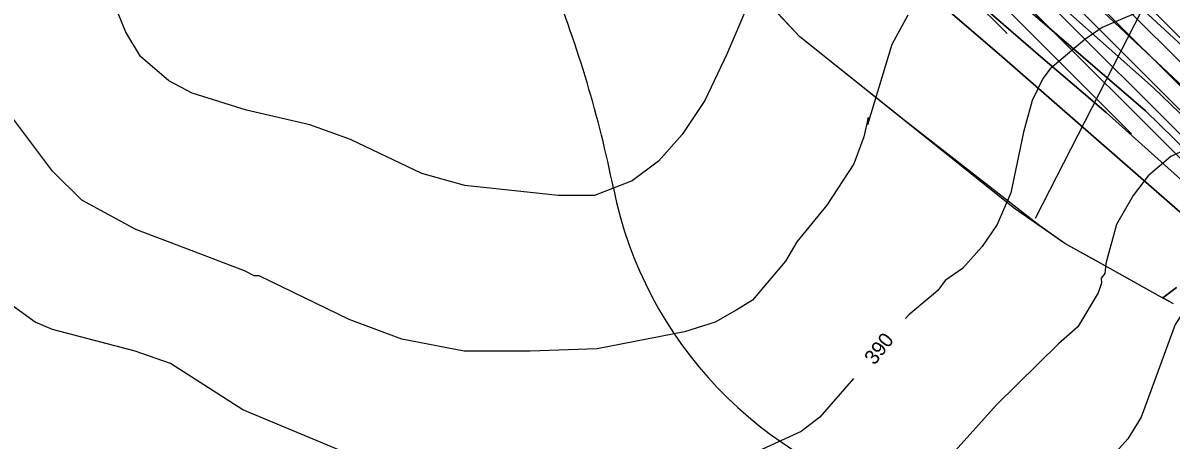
# Model space of a CAD drawing. Extents: x -510989 to -501240, y -1184665 to -1176098.
# Drawn here: x -506024.9 to -505553.2, y -1182373.4 to -1182202.2 of the extents above; entities that cross this region are included whole.
import ezdxf

# ---------------------------------------------------------------- set-up
doc = ezdxf.new("R2010")
doc.units = 0
for name, color, linetype in [('NAVRH_interakcni_prvky', 7, 'Continuous'), ('NAVRH_rozvodnice', 7, 'Continuous'), ('orna_puda', 7, 'Continuous'), ('ostatni_plocha_x_ostatni_komunikace', 7, 'Continuous'), ('popis', 7, 'Continuous'), ('STAV_erozne_ohrozene_plochy', 7, 'Continuous'), ('STAV_povodi', 7, 'Continuous'), ('vrstevnice_01', 7, 'Continuous'), ('vrstevnice_02', 7, 'Continuous'), ('vrstevnice_04', 7, 'Continuous')]:
    doc.layers.add(name, color=color, linetype=linetype)

msp = doc.modelspace()

# ---------------------------------------------------------------- linework, layer by layer
at = {"layer": 'NAVRH_interakcni_prvky'}
msp.add_lwpolyline([(-505608.99, -1182282.38), (-505565.31, -1182197.02), (-505541.49, -1182095.78), (-505537.52, -1182014.39), (-505537.52, -1181958.81), (-505551.42, -1181861.54), (-505543.48, -1181770.22), (-505601.05, -1181698.76)], dxfattribs=at)
at = {"layer": 'NAVRH_rozvodnice'}
for centre, radius, start, end in [((-506266.56, -1182367.95), 494.03, 11.4357, 21.798), ((-505619.19, -1182237), 166.46, 191.4357, 255.9859)]:
    msp.add_arc(centre, radius, start, end, dxfattribs=at)
at = {"layer": 'orna_puda'}
for points in [[(-505545.18, -1182214.83), (-505580.26, -1182182.28), (-505617.05, -1182149.56), (-505650.43, -1182121.46), (-505663.06, -1182110.4), (-505685.45, -1182090.8), (-505702.98, -1182074.96), (-505722.9, -1182057.01), (-505739.01, -1182040.64), (-505766.39, -1182010.41), (-505790.25, -1181981.36), (-505822.98, -1181943.35), (-505848.75, -1181914.84), (-505840.33, -1181901.77), (-505808.27, -1181940.23), (-505753.43, -1182008.51), (-505740.4, -1182022.58), (-505726.94, -1182036.86), (-505708.92, -1182054.97), (-505689.48, -1182072.92), (-505655.68, -1182102.08), (-505599.05, -1182150.98), (-505563.19, -1182182.97), (-505534.54, -1182209.27)], [(-505534.87, -1182240.97), (-505580.88, -1182197.95), (-505612.57, -1182169.78), (-505636.02, -1182148.91), (-505670.25, -1182118.51), (-505726.77, -1182068.32), (-505737.36, -1182058.02), (-505776.11, -1182017), (-505799.34, -1181987.39), (-505823.67, -1181958.67), (-505854.51, -1181923.82), (-505848.75, -1181914.84), (-505822.98, -1181943.35), (-505790.25, -1181981.36), (-505766.39, -1182010.41), (-505739.01, -1182040.64), (-505722.9, -1182057.01), (-505702.98, -1182074.96), (-505685.45, -1182090.8), (-505663.06, -1182110.4), (-505650.43, -1182121.46), (-505617.05, -1182149.56), (-505580.26, -1182182.28), (-505545.18, -1182214.83)], [(-505528.59, -1182272.56), (-505563.68, -1182238.3), (-505630.74, -1182180.48), (-505717.08, -1182105.45), (-505744.55, -1182080.37), (-505770.4, -1182053.98), (-505791.64, -1182029.89), (-505849.55, -1181961.49), (-505856.49, -1181953.98), (-505865.69, -1181948.03), (-505859.57, -1181935.79), (-505834.18, -1181962.22), (-505808.51, -1181992.89), (-505788.62, -1182017.4), (-505773.33, -1182035.16), (-505757.76, -1182051.76), (-505740.41, -1182069.28), (-505723.88, -1182084.02), (-505700.69, -1182105.62), (-505677.04, -1182126.17), (-505661.81, -1182139.41), (-505615.05, -1182180.23), (-505560.4, -1182228.84), (-505539.1, -1182249.38)], [(-505537.28, -1182277.15), (-505579.93, -1182239.02), (-505607.85, -1182215.08), (-505651.61, -1182177.07), (-505666.68, -1182164.52), (-505700.29, -1182135.24), (-505743.49, -1182096.79), (-505760.67, -1182080.74), (-505780.03, -1182061.47), (-505816.71, -1182018.56), (-505850.67, -1181978.46), (-505871.44, -1181958.44), (-505865.69, -1181948.03), (-505856.49, -1181953.98), (-505849.55, -1181961.49), (-505791.64, -1182029.89), (-505770.4, -1182053.98), (-505744.55, -1182080.37), (-505717.08, -1182105.45), (-505630.74, -1182180.48), (-505563.68, -1182238.3), (-505528.59, -1182272.56)], [(-505505.38, -1182318.31), (-505623.88, -1182215), (-505682.19, -1182164.88), (-505732.29, -1182121.93), (-505752.85, -1182103.56), (-505766.92, -1182090.9), (-505796.61, -1182059.91), (-505846.92, -1182000.9), (-505876.17, -1181968.64), (-505871.44, -1181958.44), (-505850.67, -1181978.46), (-505816.71, -1182018.56), (-505780.03, -1182061.47), (-505760.67, -1182080.74), (-505743.49, -1182096.79), (-505700.29, -1182135.24), (-505666.68, -1182164.52), (-505651.61, -1182177.07), (-505607.85, -1182215.08), (-505579.93, -1182239.02), (-505537.28, -1182277.15)], [(-505682.19, -1182164.88), (-505623.88, -1182215), (-505505.38, -1182318.31)], [(-505551.03, -1182310.8), (-505556.64, -1182315.12), (-505557.61, -1182314.6), (-505570.68, -1182307.26), (-505596.82, -1182292.75), (-505617.49, -1182278.33), (-505705.75, -1182207.82), (-505744.09, -1182166.53)], [(-505539.1, -1182249.38), (-505560.4, -1182228.84), (-505615.05, -1182180.23)], [(-505580.88, -1182197.95), (-505534.87, -1182240.97)]]:
    msp.add_lwpolyline(points, dxfattribs=at)
at = {"layer": 'ostatni_plocha_x_ostatni_komunikace'}
msp.add_lwpolyline([(-505552.97, -1182317.1), (-505556.64, -1182315.12), (-505551.03, -1182310.8)], dxfattribs=at)
at = {"layer": 'popis'}
msp.add_lwpolyline([(-505552.21, -1182317.51), (-505557.61, -1182314.6), (-505583.75, -1182300.01), (-505596.82, -1182292.75), (-505607.16, -1182285.54), (-505661.62, -1182243.07), (-505705.75, -1182207.82), (-505755.48, -1182155.02)], dxfattribs=at)
at = {"layer": 'STAV_erozne_ohrozene_plochy'}
for p, q in [((-505764.49, -1181993.31), (-505399.41, -1182358.39)), ((-505767.1, -1182000.6), (-505413.84, -1182353.86)), ((-505769.71, -1182007.89), (-505428.27, -1182349.33)), ((-505772.31, -1182015.18), (-505442.7, -1182344.8)), ((-505774.92, -1182022.48), (-505467.22, -1182330.18)), ((-505777.53, -1182029.77), (-505518.33, -1182288.97)), ((-505780.14, -1182037.06), (-505569.44, -1182247.76)), ((-505782.75, -1182044.35), (-505620.55, -1182206.55))]:
    msp.add_line(p, q, dxfattribs=at)
at = {"layer": 'STAV_povodi'}
for centre, radius, start, end in [((-506266.56, -1182367.95), 494.03, 11.4357, 21.798), ((-505619.19, -1182237), 166.46, 191.4357, 255.9859)]:
    msp.add_arc(centre, radius, start, end, dxfattribs=at)
at = {"layer": 'vrstevnice_01'}
for points in [[(-505710.5, -1182156), (-505735.69, -1182215), (-505744.81, -1182234), (-505754.09, -1182248), (-505763.81, -1182259), (-505774.59, -1182267), (-505790.09, -1182273), (-505805, -1182273), (-505843.41, -1182269), (-505861, -1182264), (-505890.31, -1182250), (-505907.09, -1182244), (-505933, -1182238), (-505955.31, -1182231), (-505965, -1182226), (-505976.59, -1182216), (-505982.59, -1182206), (-505988.59, -1182191)], [(-505550.09, -1182192), (-505567.41, -1182198), (-505581.5, -1182204), (-505588.69, -1182209), (-505602.91, -1182221), (-505605.91, -1182225), (-505610.31, -1182234), (-505613.81, -1182247), (-505619.09, -1182272), (-505624.69, -1182285), (-505630.81, -1182294), (-505638.91, -1182303), (-505646, -1182308), (-505649.09, -1182312), (-505652.59, -1182315), (-505660.91, -1182322), (-505662.28, -1182323.58)], [(-505492.59, -1182308), (-505514.69, -1182305), (-505525.5, -1182305), (-505535.09, -1182309), (-505545.69, -1182317), (-505551.59, -1182326), (-505565.5, -1182364), (-505571, -1182373), (-505587.19, -1182391), (-505591, -1182394), (-505605, -1182410), (-505606, -1182412), (-505609.59, -1182416), (-505616.31, -1182426), (-505620.5, -1182434), (-505629.31, -1182444), (-505634.54, -1182452.2)], [(-505683.76, -1182348.23), (-505697.5, -1182364), (-505705.19, -1182370), (-505722.81, -1182378), (-505743.31, -1182382), (-505765.5, -1182384), (-505784.41, -1182388), (-505809.09, -1182394), (-505840.69, -1182397), (-505852.09, -1182396), (-505869.91, -1182390), (-505891.5, -1182379), (-505934.5, -1182361), (-505964.31, -1182342), (-505978.81, -1182337), (-506012.69, -1182328), (-506019.91, -1182325), (-506035.31, -1182314)]]:
    msp.add_lwpolyline(points, dxfattribs=at)
at = {"layer": 'vrstevnice_02'}
for points in [[(-505661.41, -1182199), (-505668, -1182211), (-505678, -1182244), (-505677.69, -1182241), (-505679.41, -1182249), (-505683.5, -1182260), (-505694.59, -1182277), (-505707, -1182292), (-505711.69, -1182300), (-505725.19, -1182316), (-505731.59, -1182320), (-505740.5, -1182325), (-505753.09, -1182329), (-505789, -1182336), (-505816.59, -1182337), (-505820.59, -1182337), (-505843.59, -1182337), (-505869.19, -1182332), (-505890.91, -1182324), (-505927.81, -1182306), (-505929.91, -1182306), (-505933.81, -1182304), (-505957.5, -1182295), (-505978.5, -1182287), (-506000.69, -1182275), (-506012.81, -1182263), (-506034.69, -1182234)], [(-505540.5, -1182251), (-505553.31, -1182257), (-505562.59, -1182265), (-505568.81, -1182273), (-505575.69, -1182285), (-505580.09, -1182301), (-505580.41, -1182305), (-505581.91, -1182307), (-505581.81, -1182309), (-505583.19, -1182313), (-505591.5, -1182327), (-505599.5, -1182334), (-505624.91, -1182359), (-505649.19, -1182386), (-505649.81, -1182387), (-505669.19, -1182410), (-505684.09, -1182423), (-505692.11, -1182428.31)]]:
    msp.add_lwpolyline(points, dxfattribs=at)

# ---------------------------------------------------------------- texts
at = {"layer": 'vrstevnice_04'}
msp.add_text('390', height=6, rotation=51.8638, dxfattribs=at).set_placement((-505675.05, -1182342.99))

doc.saveas('drawing.dxf')
